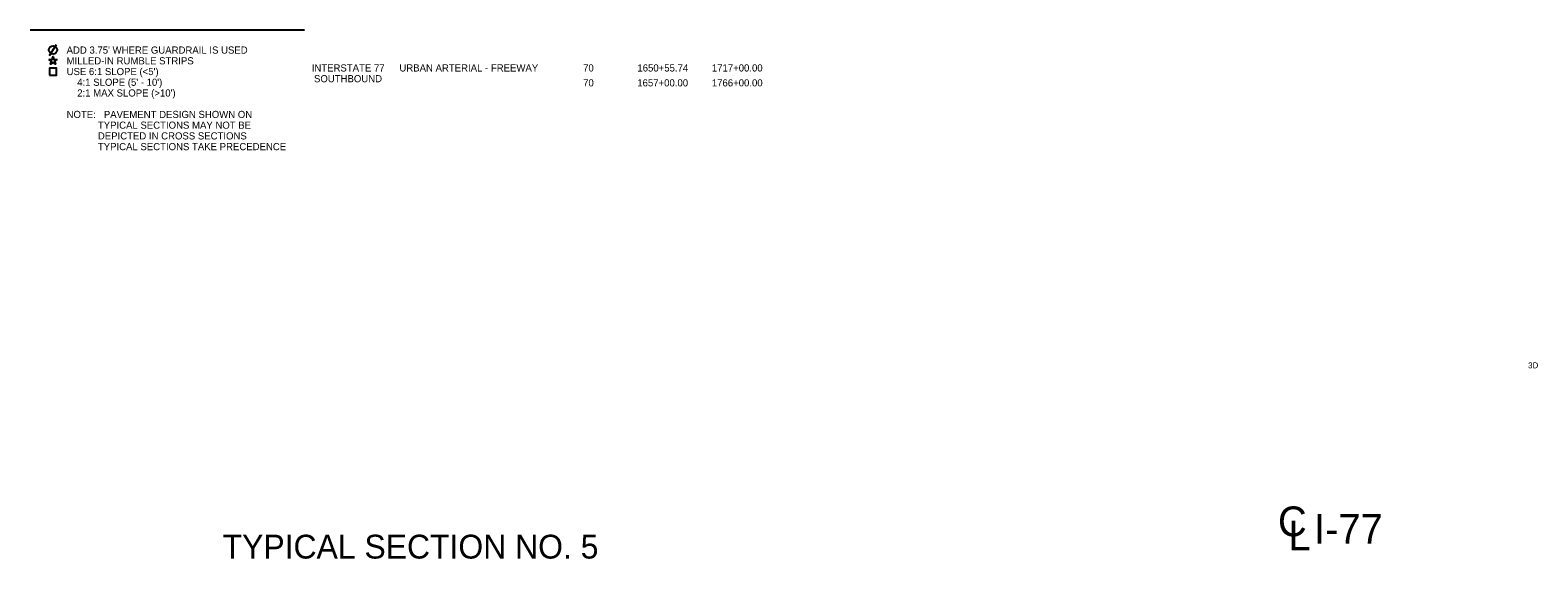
# Model space of a CAD drawing. Extents: x 2003207 to 2014043, y 843846 to 860154.
# Drawn here: x 2013655.8 to 2013782.1, y 844532.9 to 844577.2 of the extents above; entities that cross this region are included whole.
import ezdxf

# ---------------------------------------------------------------- set-up
doc = ezdxf.new("R2010")
doc.units = 0
for name, color, linetype in [('RD_EX_Road_txCode', 7, 'Continuous'), ('RD_SHT_Bndy', 7, 'Continuous'), ('RD_SHT_TX', 7, 'Continuous'), ('RD_TX_Misc1', 7, 'Continuous'), ('RD_TX_TypSect', 7, 'Continuous')]:
    doc.layers.add(name, color=color, linetype=linetype)

msp = doc.modelspace()

# ---------------------------------------------------------------- linework, layer by layer
at = {"layer": 'RD_EX_Road_txCode'}
msp.add_line((2013657.38, 844575.11), (2013657.95, 844576.05), dxfattribs=at)
for points in [[(2013657.33, 844574.79), (2013657.59, 844574.79), (2013657.67, 844575.03), (2013657.75, 844574.79), (2013658, 844574.79), (2013657.79, 844574.64), (2013657.87, 844574.4), (2013657.67, 844574.54), (2013657.46, 844574.4), (2013657.54, 844574.64)], [(2013657.37, 844573.45), (2013657.97, 844573.45), (2013657.97, 844574.05), (2013657.37, 844574.05)]]:
    msp.add_lwpolyline(points, close=True, dxfattribs=at)
msp.add_circle((2013657.67, 844575.58), 0.35, dxfattribs=at)
at = {"layer": 'RD_SHT_Bndy'}
msp.add_line((2013678.75, 844577.24), (2013655.75, 844577.24), dxfattribs=at)

# ---------------------------------------------------------------- texts
at = {"layer": 'RD_EX_Road_txCode'}
for s, p in [("ADD 3.75' WHERE GUARDRAIL IS USED", (2013658.81, 844575.27)), ('MILLED-IN RUMBLE STRIPS', (2013658.81, 844574.37)), ("USE 6:1 SLOPE (<5')", (2013658.81, 844573.47)), ("    4:1 SLOPE (5' - 10')", (2013658.81, 844572.57)), ("    2:1 MAX SLOPE (>10')", (2013658.81, 844571.67)), ('NOTE:   PAVEMENT DESIGN SHOWN ON', (2013658.81, 844569.87)), (' TYPICAL SECTIONS MAY NOT BE ', (2013661.21, 844568.97)), (' DEPICTED IN CROSS SECTIONS', (2013661.21, 844568.07)), (' TYPICAL SECTIONS TAKE PRECEDENCE', (2013661.21, 844567.17))]:
    msp.add_text(s, height=0.6, dxfattribs=at).set_placement(p)
at = {"layer": 'RD_SHT_TX'}
for s, height, p in [('INTERSTATE 77', 0.6, (2013679.36, 844573.77)), ('URBAN ARTERIAL - FREEWAY', 0.6, (2013686.71, 844573.77)), ('70', 0.6, (2013702.11, 844573.77)), ('1650+55.74', 0.6, (2013706.66, 844573.77)), ('1717+00.00', 0.6, (2013712.9, 844573.77)), ('SOUTHBOUND', 0.6, (2013679.55, 844572.87)), ('70', 0.6, (2013702.11, 844572.52)), ('1657+00.00', 0.6, (2013706.65, 844572.52)), ('1766+00.00', 0.6, (2013712.9, 844572.52)), ('3D', 0.5, (2013781.33, 844548.87))]:
    msp.add_text(s, height=height, dxfattribs=at).set_placement(p)
at = {"layer": 'RD_TX_Misc1'}
for s, p in [('C', (2013760.36, 844534.78)), ('L', (2013761.24, 844533.6)), ('I-77', (2013763.39, 844534.15))]:
    msp.add_text(s, height=2.5, dxfattribs=at).set_placement(p)
at = {"layer": 'RD_TX_TypSect'}
msp.add_text('TYPICAL SECTION NO. 5', height=2, dxfattribs=at).set_placement((2013671.89, 844532.91))

doc.saveas('drawing.dxf')
